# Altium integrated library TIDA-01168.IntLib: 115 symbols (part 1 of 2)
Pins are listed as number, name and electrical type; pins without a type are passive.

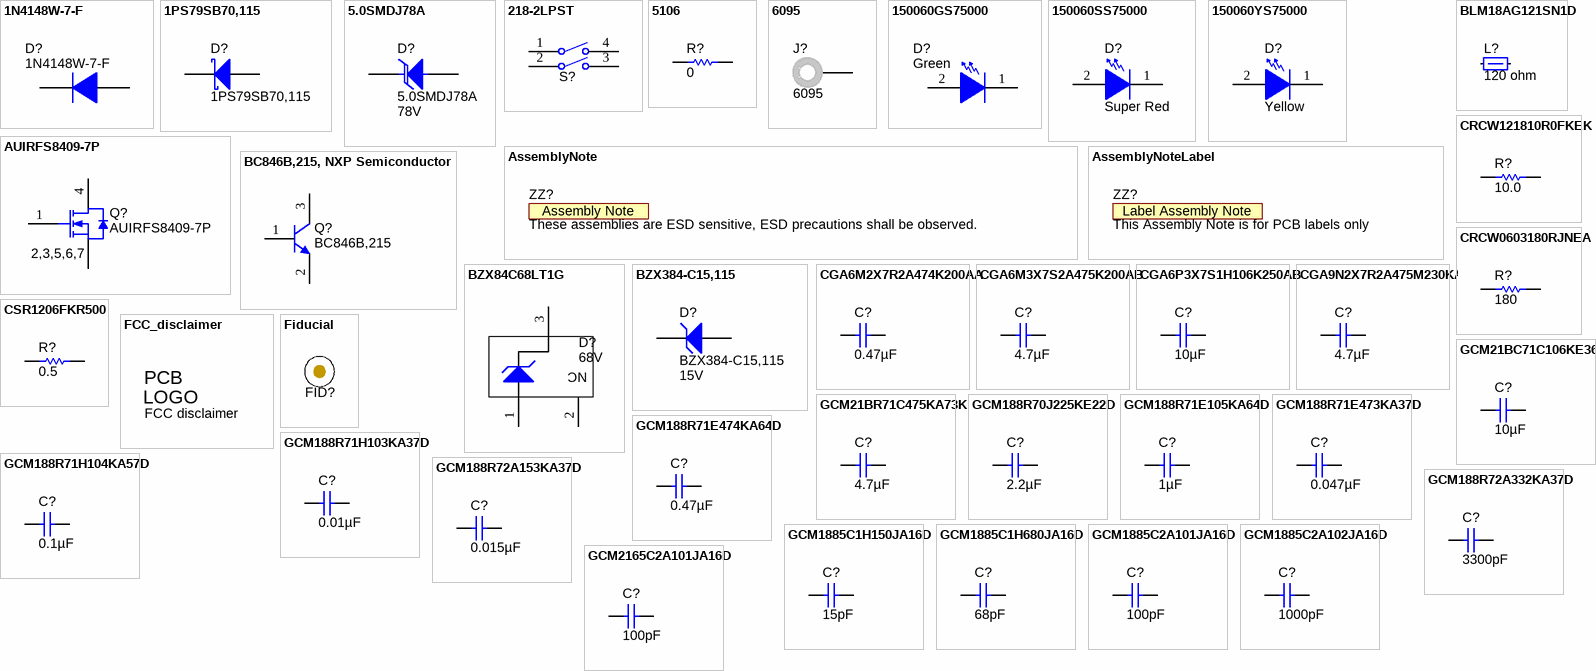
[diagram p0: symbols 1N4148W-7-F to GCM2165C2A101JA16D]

## 1N4148W-7-F
designator D?
Diode, Ultrafast, 100 V, 0.15 A, SOD-123; Manufacturer: Diodes Inc.; U/M: EA; Vf_V: 1.25; Value: 100V; Value1: 0.15A; Value2: 1.25V; Io_A: 0.15; Vr_V: 100; TJmax_C: 150; SizeAreaWB_mm2: 13.095; SizeArea_mm2: 6.545; SizeX_mm: 3.85; SizeY_mm: 1.7; SizeZ_mm: 1.35; AEC Category: Q101
signal-integrity model Diode
simulation model 1N4148W
footprint SOD-123
pins: 1 K, 2 A

## 1PS79SB70,115
designator D?
Diode, Schottky, 70 V, 0.07 A, SOD-523; Manufacturer: NXP Semiconductor; U/M: EA; Vf_V: 0.41; Value: 70V; Value1: 0.07A; Value2: 0.41V; Io_A: 0.07; Vr_V: 70; TJmax_C: 150; AEC Category: Q101
signal-integrity model Diode
footprint SOD-523
pins: 1 K, 2 A

## 5.0SMDJ78A
designator D?  value 78V
Diode, TVS, Uni, 78 V, 126 Vc, SMC; Manufacturer: Littelfuse; U/M: EA; Power_W: 6.5; Vr_V: 78; Value1: 6.5W; RJA_CperW: 75; SizeAreaWB_mm2: 83.2686; SizeArea_mm2: 50.5686; SizeX_mm: 8.13; SizeY_mm: 6.22; SizeZ_mm: 2.6; AEC Category: Q101
footprint SMC
pins: 1 K, 2 A

## 218-2LPST
designator S?  (value not drawn)
Switch, SPST, 2 Pos, 25mA, 24VDC, SMD; Manufacturer: CTS Electrocomponents; SymbolCreator: Altium; VDC_V: 24; SwitchFunction: Off-On; PositionCount: 2; CurrentRating_mA: 25
footprint SW_218-2LP
pins: 1, 2, 3, 4

## 5106
designator R?  ValueDisplayed: 0  (hidden comment: 5106)
RES, 0, 1%, 0.5 W, 0805; Manufacturer: Keystone; CompType: Resistor; Value: 0; Tolerance_%: 1; Power_W: 0.5; Value2: 0.5W; TempCo: ppm/C; SizeArea_mm2: 2.5; SizeX_mm: 2; SizeY_mm: 1.25; SizeZ_mm: 0.84; U/M: EA; AEC Category: Q200; AEC Qualified: N
signal-integrity model Resistor
simulation model Resistor
footprint 5106
pins: 1, 2

## 6095
designator J?
Standard Banana Jack, Uninsulated; Manufacturer: Keystone; CompType: Connector; SymbolCreator: a0412235
footprint Keystone_6095
pins: 1

## 150060GS75000
designator D?  value Green  (hidden comment: 150060GS75000)
LED, Green, SMD; Manufacturer: Wurth Elektronik; Type: InGaN; Vf_V: 3.2; Value2: 3.2V; Io_A: 0.02; Tjmax_C: 85; Value1: W; Angle: 140; U/M: EA
signal-integrity model Diode
footprint WL-SMCW_GREEN
pins: 1 K, 2 A

## 150060SS75000
designator D?  value Super Red  (hidden comment: 150060SS75000)
LED, Super Red, SMD; Manufacturer: Wurth Elektronik; Type: AlInGaP; Vf_V: 1.9; Value2: 1.9V; Io_A: 0.02; Value1: W; U/M: EA
signal-integrity model Diode
footprint WL-SMCW_RED
pins: 1 K, 2 A

## 150060YS75000
designator D?  value Yellow  (hidden comment: 150060YS75000)
LED, Yellow, SMD; Manufacturer: Wurth Elektronik; Type: AlInGaP; Vf_V: 2; Value2: 2V; Io_A: 0.02; Value1: W; U/M: EA
signal-integrity model Diode
footprint WL-SMCW_YELLOW
pins: 1 K, 2 A

## AssemblyNote
designator ZZ?, comment These assemblies are ESD sensitive, ESD precautions shall be observed.  (no BOM)
SymbolCreator: codlsc; CompType: AssemblyNote
footprint AssemblyNote

## AssemblyNoteLabel
designator ZZ?, comment This Assembly Note is for PCB labels only  (no BOM)
SymbolCreator: a0412235
footprint AssemblyNoteLabel

## AUIRFS8409-7P
designator Q?
MOSFET, N-CH, 40 V, 240 A, AEC-Q101, DDPAK-7; Manufacturer: Infineon Technologies; Alternate Manufacturer: None; U/M: EA; ChType: N; Value: 40V; VdsMax_V: 40; Value1: ? ohm; Value2: 305 nC; QgTyp_nC: 305; Vgs_V: 20; IdsMax_A: 240; SizeAreaWB_mm2: 209.6992; SizeArea_mm2: 154.8892; SizeX_mm: 15.245; SizeY_mm: 10.16; SizeZ_mm: 4.445; AEC Category: Q101; AEC Qualified: Y; SymbolCreator: a0412235
footprint DDPAK-7
pins: 1 G, 2 S, 3 S, 4 D, 5 S, 6 S, 7 S

## BC846B,215, NXP Semiconductor
designator Q?, comment BC846B,215
Transistor, NPN, 65 V, 0.1 A, SOT-23; Manufacturer: NXP Semiconductor; CompType: BJT; PNP: 0; NPN: 1; Vceo_V: 65; Vcesat1_V: 0.09; Value: 65 V; IcRated_A: 0.1; Value1: 0.1 A; HfeMax: 450; TaMin_C: -65; TaMax_C: 150; U/M: EA; AEC Category: Q101; AEC Qualified: N
footprint SOT-23
footprint SOT-23M
footprint SOT-23L
pins: 1 B, 2 E, 3 C

## BLM18AG121SN1D
designator L?  value 120 ohm  (hidden comment: BLM18AG121SN1D)
Ferrite Bead, 120 ohm @ 100 MHz, 0.5 A, 0603; Manufacturer: MuRata; Imax_A: 0.5; DCR_ohm: 0.18; Value1: 0.18 ohm; Value2: 0.5A; ZTyp@100MHz_Ohm: 120
footprint 0603
footprint 0603M
footprint 0603L
footprint 0603_HV
footprint 0603S
pins: 1, 2

## BZX84C68LT1G
designator D?  value 68V  (hidden comment: BZX84C68LT1G)
Diode, Zener, 68 V, 225 mW, SOT-23; Manufacturer: ON Semiconductor; U/M: EA; Power_W: 0.225; Vz_V: 68; Value1: 0.225W; RJA_CperW: 500; SizeAreaWB_mm2: 14; SizeArea_mm2: 7.5; SizeX_mm: 2.5; SizeY_mm: 3; SizeZ_mm: 1.1; AEC Category: Q101; AEC Qualified: N
signal-integrity model Diode
footprint SOT-23
footprint SOT-23M
footprint SOT-23L
pins: 1 A, 2 NC, 3 K
1 alternate drawing of the same symbol

## BZX384-C15,115
designator D?  value 15V
Diode, Zener, 15 V, 300 mW, SOD-323; Manufacturer: NXP Semiconductor; U/M: EA; Value1: 0.3W; AEC Category: Q101; SymbolCreator: a0412235; Power_W: 0.3; Vz_V: 15; RJA_CperW: 415; SizeAreaWB_mm2: 8.695; SizeArea_mm2: 3.645; SizeX_mm: 2.7; SizeY_mm: 1.35; SizeZ_mm: 1
signal-integrity model Diode
footprint SOD-323
pins: 1 K, 2 A

## CGA6M2X7R2A474K200AA
designator C?  ValueDisplayed: 0.47µF  (hidden comment: CGA6M2X7R2A474K200AA)
CAP, CERM, 0.47 µF, 100 V, +/- 10%, X7R, AEC-Q200 Grade 1, 1210; Manufacturer: TDK; Polarized: N; CompType: Capacitor; Value: 0.47uF; U/M: EA; Cap_F: 0.00000047; Tolerance_%: 10; ESR_ohm: 0.009164; Value1: 0.009164 ohm; VDC_V: 100; Value2: 100V; IRMS_A: 2.43674; TaMin_C: -55; TaMax_C: 125; Cap_Case: 1210_220; SizeArea_mm2: 8; SizeAreaWB_mm2: 14.7; SizeX_mm: 3.2; SizeY_mm: 2.5; SizeZ_mm: 2.2; AEC Category: Q200; AEC Qualified: Y; AEC Grade: 1
signal-integrity model Cap
simulation model Cap
footprint 1210_220
footprint 1210_220M
footprint 1210_220L
pins: 1, 2

## CGA6M3X7S2A475K200AB
designator C?  ValueDisplayed: 4.7µF  (hidden comment: CGA6M3X7S2A475K200AB)
CAP, CERM, 4.7 µF, 100 V, +/- 10%, X7S, AEC-Q200 Grade 1, 1210; Manufacturer: TDK; Polarized: N; CompType: Capacitor; Value: 4.7uF; U/M: EA; Cap_F: 0.0000047; Tolerance_%: 10; ESR_ohm: 0.004236; Value1: 0.004236 ohm; VDC_V: 100; Value2: 100V; IRMS_A: 3.57337; TaMin_C: -55; TaMax_C: 125; Cap_Case: 1210_220; SizeArea_mm2: 8; SizeAreaWB_mm2: 14.7; SizeX_mm: 3.2; SizeY_mm: 2.5; SizeZ_mm: 2.2; AEC Category: Q200; AEC Qualified: Y; AEC Grade: 1
signal-integrity model Cap
simulation model Cap
footprint 1210_220
footprint 1210_220M
footprint 1210_220L
pins: 1, 2

## CGA6P3X7S1H106K250AB
designator C?  ValueDisplayed: 10µF  (hidden comment: CGA6P3X7S1H106K250AB)
CAP, CERM, 10 µF, 50 V, +/- 10%, X7S, AEC-Q200 Grade 1, 1210; Manufacturer: TDK; Polarized: N; CompType: Capacitor; Value: 10uF; U/M: EA; Cap_F: 0.00001; Tolerance_%: 10; ESR_ohm: 0.002827; Value1: 0.002827 ohm; VDC_V: 50; Value2: 50V; IRMS_A: 4.37286; TaMin_C: -55; TaMax_C: 125; Cap_Case: 1210_280; SizeArea_mm2: 8; SizeAreaWB_mm2: 14.7; SizeX_mm: 3.2; SizeY_mm: 2.5; SizeZ_mm: 2.8; AEC Category: Q200; AEC Qualified: Y; AEC Grade: 1
signal-integrity model Cap
simulation model Cap
footprint 1210_280
pins: 1, 2

## CGA9N2X7R2A475M230KA
designator C?  ValueDisplayed: 4.7µF  (hidden comment: CGA9N2X7R2A475M230KA)
CAP, CERM, 4.7 µF, 100 V, +/- 20%, X7R, AEC-Q200 Grade 1,; Manufacturer: TDK; Polarized: N; CompType: Capacitor; Value: 4.7uF; U/M: EA; Cap_F: 0.0000047; Tolerance_%: 20; Value1: Unknown; VDC_V: 100; Value2: 100V; TaMin_C: -55; TaMax_C: 125; Cap_Case: 2220; SizeArea_mm2: 28.5; SizeAreaWB_mm2: 53.9; SizeX_mm: 5.7; SizeY_mm: 5; SizeZ_mm: 2.5; AEC Category: Q200; AEC Qualified: Y; AEC Grade: 1
signal-integrity model Cap
simulation model Cap
footprint 2220_250
footprint 2220_250M
footprint 2220_250L
pins: 1, 2

## CRCW121810R0FKEK
designator R?  ValueDisplayed: 10.0  (hidden comment: CRCW121810R0FKEK)
RES, 10.0, 1%, 1 W, 1218; Manufacturer: Vishay-Dale; CompType: Resistor; Value: 10.0; Res_ohm: 10; Value_Code: 10R0; Tolerance_%: 1; Value2: 1W; VDC_V: 200; TempCo: 100 ppm/C; SizeArea_mm2: 14.72; SizeAreaWB_mm2: 23.52; SizeX_mm: 3.2; SizeY_mm: 4.6; SizeZ_mm: 0.6; EIA_Code: E96; U/M: EA; AEC Category: Q200
signal-integrity model Resistor
simulation model Resistor
footprint 1218
pins: 1, 2

## CRCW0603180RJNEA
designator R?  ValueDisplayed: 180  (hidden comment: CRCW0603180RJNEA)
RES, 180, 5%, 0.1 W, 0603; Manufacturer: Vishay-Dale; CompType: Resistor; Value: 180; Value_Code: 180R; Tolerance_%: 5; Power_W: 0.1; Value2: 0.1W; VDC_V: 75; TempCo: 200 ppm/C; EIA_Code: E24; U/M: EA; AEC Category: Q200; SizeArea_mm2: 1.28; SizeX_mm: 1.6; SizeY_mm: 0.8; SizeZ_mm: 1
signal-integrity model Resistor
simulation model Resistor
footprint 0603
footprint 0603M
footprint 0603L
footprint 0603_HV
footprint 0603S
pins: 1, 2

## CSR1206FKR500
designator R?  ValueDisplayed: 0.5  (hidden comment: CSR1206FKR500)
RES, 0.5, 1%, 0.5 W, 1206; Manufacturer: Stackpole Electronics Inc; CompType: Resistor; Value: 0.5; Value_Code: R500; Tolerance_%: 1; Value2: 0.5W; TempCo: 100 ppm/C; U/M: EA; AEC Category: Q200; SizeArea_mm2: 5.12; SizeX_mm: 3.2; SizeY_mm: 1.6; SizeZ_mm: 1.35
signal-integrity model Resistor
simulation model Resistor
footprint 1206
footprint 1206M
footprint 1206L
pins: 1, 2

## FCC_disclaimer
designator Logo?, comment FCC disclaimer  (no BOM)
FCC_disclaimer; SymbolCreator: codlsc
footprint FCC_disclaimer
footprint FCC_disclaimer_stacked

## Fiducial
designator FID?  (value not drawn)
Fiducial mark.  There is nothing to buy or mount.; SymbolCreator: codlsc
footprint Fiducial10-30
footprint Fiducial10-20
footprint Fiducial15-30
footprint Fiducial20-40
footprint Fiducial6.4-20

## GCM21BC71C106KE36L
designator C?  ValueDisplayed: 10µF  (hidden comment: GCM21BC71C106KE36L)
CAP, CERM, 10 µF, 16 V, +/- 10%, X7S, AEC-Q200 Grade 1, 0805; Manufacturer: MuRata; Polarized: N; CompType: Capacitor; Value: 10uF; U/M: EA; Cap_F: 0.00001; Tolerance_%: 10; Value1: Unknown; VDC_V: 16; Value2: 16V; TaMin_C: -55; TaMax_C: 125; Cap_Case: 0805; AEC Category: Q200; AEC Qualified: Y; AEC Grade: 1; SizeArea_mm2: 2.5; SizeAreaWB_mm2: 6.75; SizeX_mm: 2; SizeY_mm: 1.25; SizeZ_mm: 1.45
signal-integrity model Cap
simulation model Cap
footprint 0805_HV
footprint 0805_HV1
footprint 0805
footprint 0805M
footprint 0805L
pins: 1, 2

## GCM21BR71C475KA73K
designator C?  ValueDisplayed: 4.7µF  (hidden comment: GCM21BR71C475KA73K)
CAP, CERM, 4.7 µF, 16 V, +/- 10%, X7R, AEC-Q200 Grade 1, 0805; Manufacturer: MuRata; Polarized: N; CompType: Capacitor; Value: 4.7uF; U/M: EA; Cap_F: 0.0000047; Tolerance_%: 10; Value1: Unknown; VDC_V: 16; Value2: 16V; TaMin_C: -55; TaMax_C: 125; Cap_Case: 0805; AEC Category: Q200; AEC Qualified: Y; AEC Grade: 1; SizeArea_mm2: 2.5; SizeAreaWB_mm2: 6.75; SizeX_mm: 2; SizeY_mm: 1.25; SizeZ_mm: 1.45
signal-integrity model Cap
simulation model Cap
footprint 0805_HV
footprint 0805_HV1
footprint 0805
footprint 0805M
footprint 0805L
pins: 1, 2

## GCM188R70J225KE22D
designator C?  ValueDisplayed: 2.2µF  (hidden comment: GCM188R70J225KE22D)
CAP, CERM, 2.2 µF, 6.3 V, +/- 10%, X7R, AEC-Q200 Grade 1, 0603; Manufacturer: MuRata; Polarized: N; CompType: Capacitor; Value: 2.2uF; U/M: EA; Cap_F: 0.0000022; Tolerance_%: 10; Value1: Unknown; VDC_V: 6.3; Value2: 6.3V; TaMin_C: -55; TaMax_C: 125; Cap_Case: 0603; AEC Category: Q200; AEC Qualified: Y; AEC Grade: 1; SizeArea_mm2: 1.28; SizeAreaWB_mm2: 4.68; SizeX_mm: 1.6; SizeY_mm: 0.8
signal-integrity model Cap
simulation model Cap
footprint 0603
footprint 0603M
footprint 0603L
footprint 0603_HV
footprint 0603S
pins: 1, 2

## GCM188R71E105KA64D
designator C?  ValueDisplayed: 1µF  (hidden comment: GCM188R71E105KA64D)
CAP, CERM, 1 µF, 25 V, +/- 10%, X7R, AEC-Q200 Grade 1, 0603; Manufacturer: MuRata; Polarized: N; CompType: Capacitor; Value: 1uF; U/M: EA; Cap_F: 0.000001; Tolerance_%: 10; Value1: Unknown; VDC_V: 25; Value2: 25V; TaMin_C: -55; TaMax_C: 125; Cap_Case: 0603; AEC Category: Q200; AEC Qualified: Y; AEC Grade: 1; SizeArea_mm2: 1.28; SizeAreaWB_mm2: 4.68; SizeX_mm: 1.6; SizeY_mm: 0.8
signal-integrity model Cap
simulation model Cap
footprint 0603
footprint 0603M
footprint 0603L
footprint 0603_HV
footprint 0603S
pins: 1, 2

## GCM188R71E473KA37D
designator C?  ValueDisplayed: 0.047µF  (hidden comment: GCM188R71E473KA37D)
CAP, CERM, 0.047 µF, 25 V, +/- 10%, X7R, AEC-Q200 Grade 1, 0603; Manufacturer: MuRata; Polarized: N; CompType: Capacitor; Value: 0.047uF; U/M: EA; Cap_F: 0.000000047; Tolerance_%: 10; Value1: Unknown; VDC_V: 25; Value2: 25V; TaMin_C: -55; TaMax_C: 125; Cap_Case: 0603; AEC Category: Q200; AEC Qualified: Y; AEC Grade: 1; SizeArea_mm2: 1.28; SizeAreaWB_mm2: 4.68; SizeX_mm: 1.6; SizeY_mm: 0.8
signal-integrity model Cap
simulation model Cap
footprint 0603
footprint 0603M
footprint 0603L
footprint 0603_HV
footprint 0603S
pins: 1, 2

## GCM188R71E474KA64D
designator C?  ValueDisplayed: 0.47µF  (hidden comment: GCM188R71E474KA64D)
CAP, CERM, 0.47 µF, 25 V, +/- 10%, X7R, AEC-Q200 Grade 1, 0603; Manufacturer: MuRata; Polarized: N; CompType: Capacitor; Value: 0.47uF; U/M: EA; Cap_F: 0.00000047; Tolerance_%: 10; Value1: Unknown; VDC_V: 25; Value2: 25V; TaMin_C: -55; TaMax_C: 125; Cap_Case: 0603; AEC Category: Q200; AEC Qualified: Y; AEC Grade: 1; SizeArea_mm2: 1.28; SizeAreaWB_mm2: 4.68; SizeX_mm: 1.6; SizeY_mm: 0.8
signal-integrity model Cap
simulation model Cap
footprint 0603
footprint 0603M
footprint 0603L
footprint 0603_HV
footprint 0603S
pins: 1, 2

## GCM188R71H103KA37D
designator C?  ValueDisplayed: 0.01µF  (hidden comment: GCM188R71H103KA37D)
CAP, CERM, 0.01 µF, 50 V, +/- 10%, X7R, AEC-Q200 Grade 1, 0603; Manufacturer: MuRata; Polarized: N; CompType: Capacitor; Value: 0.01uF; U/M: EA; Cap_F: 0.00000001; Tolerance_%: 10; Value1: Unknown; VDC_V: 50; Value2: 50V; TaMin_C: -55; TaMax_C: 125; Cap_Case: 0603; SizeArea_mm2: 1.28; SizeAreaWB_mm2: 4.68; SizeX_mm: 1.6; SizeY_mm: 0.8; SizeZ_mm: 1; AEC Category: Q200; AEC Qualified: Y
signal-integrity model Cap
simulation model Cap
footprint 0603
footprint 0603M
footprint 0603L
footprint 0603_HV
footprint 0603S
pins: 1, 2

## GCM188R71H104KA57D
designator C?  ValueDisplayed: 0.1µF  (hidden comment: GCM188R71H104KA57D)
CAP, CERM, 0.1 µF, 50 V, +/- 10%, X7R, 0603; Manufacturer: MuRata; Polarized: N; CompType: Capacitor; Value: 0.1uF; U/M: EA; Cap_F: 0.0000001; Tolerance_%: 10; ESR_ohm: 0.02; Value1: 0.02 ohm; VDC_V: 50; Value2: 50V; IRMS_A: 1.84; TaMin_C: -55; TaMax_C: 125; Cap_Case: 0603; SizeArea_mm2: 1.28; SizeAreaWB_mm2: 4.68; SizeX_mm: 1.6; SizeY_mm: 0.8; SizeZ_mm: 1; AEC Category: Q200
signal-integrity model Cap
simulation model Cap
footprint 0603
footprint 0603M
footprint 0603L
footprint 0603_HV
footprint 0603S
pins: 1, 2

## GCM188R72A153KA37D
designator C?  ValueDisplayed: 0.015µF  (hidden comment: GCM188R72A153KA37D)
CAP, CERM, 0.015 µF, 100 V, +/- 10%, X7R, AEC-Q200 Grade 1, 0603; Manufacturer: MuRata; Polarized: N; CompType: Capacitor; Value: 0.015uF; U/M: EA; Cap_F: 0.000000015; Tolerance_%: 10; Value1: Unknown; VDC_V: 100; Value2: 100V; TaMin_C: -55; TaMax_C: 125; Cap_Case: 0603; SizeArea_mm2: 1.28; SizeAreaWB_mm2: 4.68; SizeX_mm: 1.6; SizeY_mm: 0.8; SizeZ_mm: 1; AEC Category: Q200; AEC Qualified: Y
signal-integrity model Cap
simulation model Cap
footprint 0603
footprint 0603M
footprint 0603L
footprint 0603_HV
footprint 0603S
pins: 1, 2

## GCM188R72A332KA37D
designator C?  ValueDisplayed: 3300pF  (hidden comment: GCM188R72A332KA37D)
CAP, CERM, 3300 pF, 100 V, +/- 10%, X7R, AEC-Q200 Grade 1, 0603; Manufacturer: MuRata; Polarized: N; CompType: Capacitor; Value: 3300pF; U/M: EA; Cap_F: 0.0000000033; Tolerance_%: 10; Value1: Unknown; VDC_V: 100; Value2: 100V; TaMin_C: -55; TaMax_C: 125; Cap_Case: 0603; SizeArea_mm2: 1.28; SizeAreaWB_mm2: 4.68; SizeX_mm: 1.6; SizeY_mm: 0.8; SizeZ_mm: 1; AEC Category: Q200; AEC Qualified: Y
signal-integrity model Cap
simulation model Cap
footprint 0603
footprint 0603M
footprint 0603L
footprint 0603_HV
footprint 0603S
pins: 1, 2

## GCM1885C1H150JA16D
designator C?  ValueDisplayed: 15pF  (hidden comment: GCM1885C1H150JA16D)
CAP, CERM, 15 pF, 50 V, +/- 5%, C0G/NP0, AEC-Q200 Grade 1, 0603; Manufacturer: MuRata; Polarized: N; CompType: Capacitor; Value: 15pF; U/M: EA; Cap_F: 0.000000000015; Tolerance_%: 5; Value1: Unknown; VDC_V: 50; Value2: 50V; TaMin_C: -55; TaMax_C: 125; Cap_Case: 0603; SizeArea_mm2: 1.28; SizeAreaWB_mm2: 4.68; SizeX_mm: 1.6; SizeY_mm: 0.8; SizeZ_mm: 1; AEC Category: Q200; AEC Qualified: Y
signal-integrity model Cap
simulation model Cap
footprint 0603
footprint 0603M
footprint 0603L
footprint 0603_HV
footprint 0603S
pins: 1, 2

## GCM1885C1H680JA16D
designator C?  ValueDisplayed: 68pF  (hidden comment: GCM1885C1H680JA16D)
CAP, CERM, 68 pF, 50 V, +/- 5%, C0G/NP0, AEC-Q200 Grade 1, 0603; Manufacturer: MuRata; Polarized: N; CompType: Capacitor; Value: 68pF; U/M: EA; Cap_F: 0.000000000068; Tolerance_%: 5; Value1: Unknown; VDC_V: 50; Value2: 50V; TaMin_C: -55; TaMax_C: 125; Cap_Case: 0603; AEC Category: Q200; AEC Qualified: Y; AEC Grade: 1
signal-integrity model Cap
simulation model Cap
footprint 0603
footprint 0603M
footprint 0603L
footprint 0603_HV
footprint 0603S
pins: 1, 2

## GCM1885C2A101JA16D
designator C?  ValueDisplayed: 100pF  (hidden comment: GCM1885C2A101JA16D)
CAP, CERM, 100 pF, 100 V, +/- 5%, C0G/NP0, AEC-Q200 Grade 1, 0603; Manufacturer: MuRata; Polarized: N; CompType: Capacitor; Value: 100pF; U/M: EA; Cap_F: 0.0000000001; Tolerance_%: 5; Value1: Unknown; VDC_V: 100; Value2: 100V; TaMin_C: -55; TaMax_C: 125; Cap_Case: 0603; SizeArea_mm2: 1.28; SizeAreaWB_mm2: 4.68; SizeX_mm: 1.6; SizeY_mm: 0.8; SizeZ_mm: 1; AEC Category: Q200; AEC Qualified: Y
signal-integrity model Cap
simulation model Cap
footprint 0603
footprint 0603M
footprint 0603L
footprint 0603_HV
footprint 0603S
pins: 1, 2

## GCM1885C2A102JA16D
designator C?  ValueDisplayed: 1000pF  (hidden comment: GCM1885C2A102JA16D)
CAP, CERM, 1000 pF, 100 V, +/- 5%, C0G/NP0, AEC-Q200 Grade 1, 0603; Manufacturer: MuRata; Polarized: N; CompType: Capacitor; Value: 1000pF; U/M: EA; Cap_F: 0.000000001; Tolerance_%: 5; Value1: Unknown; VDC_V: 100; Value2: 100V; TaMin_C: -55; TaMax_C: 125; Cap_Case: 0603; SizeArea_mm2: 1.28; SizeAreaWB_mm2: 4.68; SizeX_mm: 1.6; SizeY_mm: 0.8; SizeZ_mm: 1; AEC Category: Q200; AEC Qualified: Y
signal-integrity model Cap
simulation model Cap
footprint 0603
footprint 0603M
footprint 0603L
footprint 0603_HV
footprint 0603S
pins: 1, 2

## GCM2165C2A101JA16D
designator C?  ValueDisplayed: 100pF  (hidden comment: GCM2165C2A101JA16D)
CAP, CERM, 100 pF, 100 V, +/- 5%, C0G/NP0, AEC-Q200 Grade 1, 0805; Manufacturer: MuRata; Polarized: N; CompType: Capacitor; Value: 100pF; U/M: EA; Cap_F: 0.0000000001; Tolerance_%: 5; Value1: Unknown; VDC_V: 100; Value2: 100V; TaMin_C: -55; TaMax_C: 105; Cap_Case: 0805; SizeArea_mm2: 2.5; SizeAreaWB_mm2: 6.75; SizeX_mm: 2; SizeY_mm: 1.25; SizeZ_mm: 1.45; AEC Category: Q200; AEC Qualified: Y; AEC Grade: 1
signal-integrity model Cap
simulation model Cap
footprint 0805_HV
footprint 0805_HV1
footprint 0805
footprint 0805M
footprint 0805L
pins: 1, 2

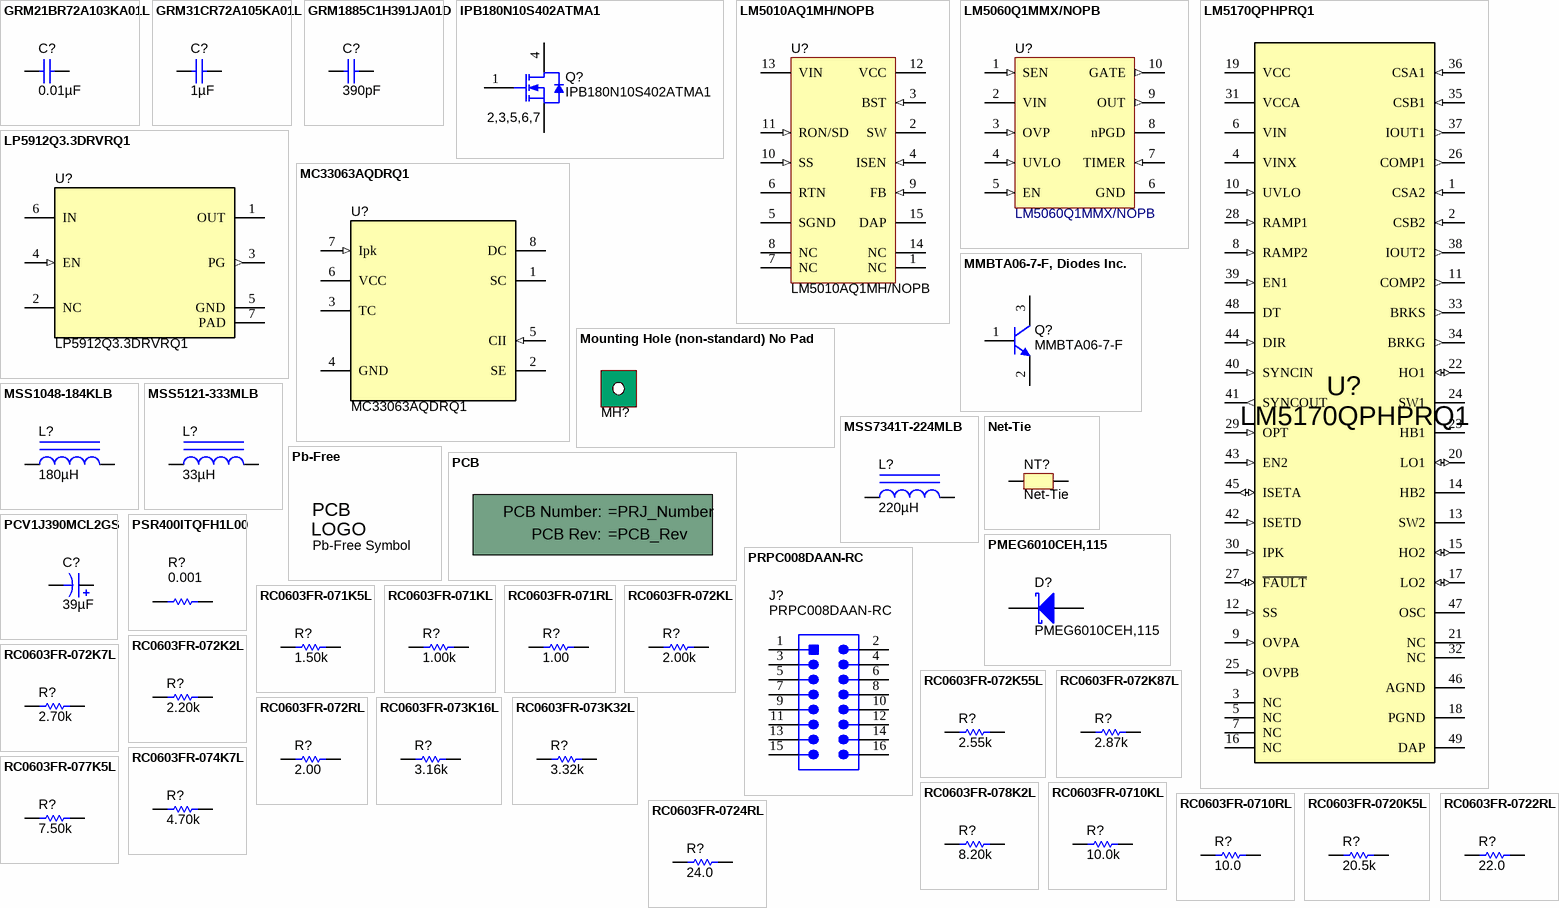
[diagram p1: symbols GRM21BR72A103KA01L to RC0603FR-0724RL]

## GRM21BR72A103KA01L
designator C?  ValueDisplayed: 0.01µF  (hidden comment: GRM21BR72A103KA01L)
CAP, CERM, 0.01 µF, 100 V, +/- 10%, X7R, 0805; Manufacturer: MuRata; Polarized: N; CompType: Capacitor; Value: 0.01uF; U/M: EA; Cap_F: 0.00000001; Tolerance_%: 10; Value1: Unknown; VDC_V: 100; Value2: 100V; TaMin_C: -55; TaMax_C: 125; Cap_Case: 0805; AEC Category: Q200; SizeArea_mm2: 2.5; SizeAreaWB_mm2: 6.75; SizeX_mm: 2; SizeY_mm: 1.25; SizeZ_mm: 1.45
signal-integrity model Cap
simulation model Cap
footprint 0805_HV
footprint 0805_HV1
footprint 0805
footprint 0805M
footprint 0805L
pins: 1, 2

## GRM31CR72A105KA01L
designator C?  ValueDisplayed: 1µF  (hidden comment: GRM31CR72A105KA01L)
CAP, CERM, 1 µF, 100 V, +/- 10%, X7R, 1206; Manufacturer: MuRata; Polarized: N; CompType: Capacitor; Value: 1uF; U/M: EA; Cap_F: 0.000001; Tolerance_%: 10; Value1: Unknown; VDC_V: 100; Value2: 100V; TaMin_C: -55; TaMax_C: 125; Cap_Case: 2220; AEC Category: Q200; SizeArea_mm2: 5.12; SizeAreaWB_mm2: 10.92; SizeX_mm: 3.2; SizeY_mm: 1.6; SizeZ_mm: 1.8
signal-integrity model Cap
simulation model Cap
footprint 1206_180
footprint 1206_180M
footprint 1206_180L
pins: 1, 2

## GRM1885C1H391JA01D
designator C?  ValueDisplayed: 390pF  (hidden comment: GRM1885C1H391JA01D)
CAP, CERM, 390 pF, 50 V, +/- 5%, C0G/NP0, 0603; Manufacturer: MuRata; Polarized: N; CompType: Capacitor; Value: 390pF; U/M: EA; Cap_F: 0.00000000039; Tolerance_%: 5; Value1: Unknown; VDC_V: 50; Value2: 50V; TaMin_C: -55; TaMax_C: 125; Cap_Case: 0603; SizeArea_mm2: 1.28; SizeAreaWB_mm2: 4.68; SizeX_mm: 1.6; SizeY_mm: 0.8; SizeZ_mm: 1; AEC Category: Q200
signal-integrity model Cap
simulation model Cap
footprint 0603
footprint 0603M
footprint 0603L
footprint 0603_HV
footprint 0603S
pins: 1, 2

## IPB180N10S402ATMA1
designator Q?
MOSFET, N-CH, 100 V, 180 A, AEC-Q101, DDPAK-7; Manufacturer: Infineon Technologies; Alternate Manufacturer: None; U/M: EA; ChType: N; Value: 100V; VdsMax_V: 100; Value1: ? ohm; Value2: 156 nC; QgTyp_nC: 156; Vgs_V: 20; IdsMax_A: 180; SizeAreaWB_mm2: 209.6992; SizeArea_mm2: 154.8892; SizeX_mm: 15.245; SizeY_mm: 10.16; SizeZ_mm: 4.445; AEC Category: Q101; AEC Qualified: Y; SymbolCreator: a0412235
footprint DDPAK-7
pins: 1 G, 2 S, 3 S, 4 D, 5 S, 6 S, 7 S

## LM5010AQ1MH/NOPB
designator U?
High Voltage 1A Step Down Switching Regulator, 14-pin TSSOP-EP, Pb-Free; Manufacturer: Texas Instruments; PackageTopMarking: NSUZXYTT*L5010A*Q1MH; PowerWise: N; CompType: Switcher
footprint MXA14A_N (TSOP, 14-Leads, Body 5x4.4mm, Pitch 0.65mm, Exposed Pad, IPC Medium Density)
footprint MXA14A_L (TSOP, 14-Leads, Body 5x4.4mm, Pitch 0.65mm, Exposed Pad, IPC High Density)
footprint MXA14A_M (TSOP, 14-Leads, Body 5x4.4mm, Pitch 0.65mm, Exposed Pad, IPC Low Density)
pins: 1 NC, 2 SW (power), 3 BST (in), 4 ISEN (in), 5 SGND (power), 6 RTN (power), 7 NC, 8 NC, 9 FB (in), 10 SS (in), 11 RON/SD (in), 12 VCC (power), 13 VIN (power), 14 NC, 15 DAP (power)

## LM5060Q1MMX/NOPB
designator U?
High-Side Protection Controller with Low Quiescent Current, 10-pin MSOP, Pb-Free; Manufacturer: Texas Instruments; PackageTopMarking: ZXTT*SZAB; PowerWise: N; CompType: Switcher
footprint MUB10A_N (TSSOP, 10-Leads, Body 3x3mm, Pitch 0.5mm, IPC Medium Density)
footprint MUB10A_L (TSSOP, 10-Leads, Body 3x3mm, Pitch 0.5mm, IPC High Density)
footprint MUB10A_M (TSSOP, 10-Leads, Body 3x3mm, Pitch 0.5mm, IPC Low Density)
pins: 1 SEN (in), 2 VIN (power), 3 OVP (in), 4 UVLO (in), 5 EN (in), 6 GND (power), 7 TIMER (in), 8 nPGD (oc), 9 OUT (out), 10 GATE (out)

## LM5170QPHPRQ1
designator U?
Dual Channel 48V-12V Bidirectional Current Controller, PHP0048D; Alternate PartNumber: LM5170QPHPTQ1; Manufacturer: Texas Instruments; SymbolCreator: Altium; SizeArea_mm2: 81; SizeAreaWB_mm2: 121; SizeX_mm: 9; SizeZ_mm: 1.2; CompType: IC; U/M: EA
footprint PHP0048D_N
footprint PHP0048D_M
footprint PHP0048D_L
pins: 1 CSA2 (in), 2 CSB2 (in), 3 NC, 4 VINX (power), 5 NC, 6 VIN (power), 7 NC, 8 RAMP2 (in), 9 OVPA (in), 10 UVLO (in), 11 COMP2 (out), 12 SS (in), 13 SW2 (power), 14 HB2 (power), 15 HO2 (io), 16 NC, 17 LO2 (io), 18 PGND (power), 19 VCC (power), 20 LO1 (io), 21 NC, 22 HO1 (io), 23 HB1 (power), 24 SW1 (power), 25 OVPB (in), 26 COMP1 (out), 27 ~{FAULT} (io), 28 RAMP1 (in), 29 OPT (in), 30 IPK (in), 31 VCCA (power), 32 NC, 33 BRKS (out), 34 BRKG (out), 35 CSB1 (in), 36 CSA1 (in), 37 IOUT1 (out), 38 IOUT2 (out), 39 EN1 (in), 40 SYNCIN (in), 41 SYNCOUT (out), 42 ISETD (in), 43 EN2 (in), 44 DIR (in), 45 ISETA (io), 46 AGND (power), 47 OSC, 48 DT, 49 DAP (power)
1 alternate drawing of the same symbol

## LP5912Q3.3DRVRQ1
designator U?
Ultra Low-Noise, 500-mA Linear Regulator for RF and Analog Circuits - Requires No Bypass Capacitor, DRV0006A; Alternate PartNumber: LP5912Q3.3DRVTQ1; Manufacturer: Texas Instruments; SymbolCreator: a0411947; SizeArea_mm2: 4; SizeAreaWB_mm2: 9; SizeX_mm: 2; SizeZ_mm: 0.8; CompType: IC; U/M: EA
footprint DRV0006A
footprint DRV0006A_NV
pins: 1 OUT (power), 2 NC, 3 PG (out), 4 EN (in), 5 GND (power), 6 IN (power), 7 PAD (power)

## MC33063AQDRQ1
designator U?
1.5-A PEAK BOOST / BUCK / INVERTING SWITCHING REGULATOR, D0008A; Manufacturer: Texas Instruments; SymbolCreator: Altium; SizeArea_mm2: 30.38; SizeAreaWB_mm2: 56.58; SizeX_mm: 4.9; SizeY_mm: 6.2; SizeZ_mm: 1.75; CompType: IC; U/M: EA
footprint D0008A_N
footprint D0008A_M
footprint D0008A_L
pins: 1 SC (oc) "Switch Collector", 2 SE (oe) "Switch Emitter", 3 TC "Timing Capacitor", 4 GND (power), 5 CII (in) "Comparator Inverting Input", 6 VCC (power), 7 Ipk (in), 8 DC (oc) "Driver Collector"

## MMBTA06-7-F, Diodes Inc.
designator Q?, comment MMBTA06-7-F
Transistor, NPN, 80 V, 0.5 A, SOT-23; Manufacturer: Diodes Inc.; CompType: BJT; PNP: 0; NPN: 1; Vceo_V: 80; Vcesat1_V: 0.25; Value: 80 V; IcRated_A: 0.5; Value1: 0.5 A; TaMin_C: -55; TaMax_C: 150; U/M: EA; AEC Category: Q101
footprint SOT-23
footprint SOT-23M
footprint SOT-23L
pins: 1 B, 2 E, 3 C

## Mounting Hole (non-standard) No Pad
designator MH?, comment MTG_NoPads  (value not drawn)  (no BOM)
PCB Mounting Hole, No Pad; Manufacturer: Any; SymbolCreator: a0412235
footprint MTG_159mil
footprint NPTH125mil
footprint NPTH109mil

## MSS1048-184KLB
designator L?  ValueDisplayed: 180µH  (hidden comment: MSS1048-184KLB)
Inductor, Shielded Drum Core, Ferrite, 180 µH, 1.02 A, 0.45 ohm, SMD; Manufacturer: Coilcraft; Value: 180uH; Ind_H: 180.0E-6; Imax_A: 1.02; Irms: 1.24A @ 40C rise; Isat: 1.02A @ 30% inductance drop; DCR_ohm: 0.45; Value2: 1.02A; AEC Category: Q200
signal-integrity model Inductor
simulation model Inductor
footprint MSS1048
pins: 1, 2

## MSS5121-333MLB
designator L?  ValueDisplayed: 33µH  (hidden comment: MSS5121-333MLB)
Inductor, Shielded Drum Core, Ferrite, 33 µH, 0.67 A, 0.48 ohm, SMD; Manufacturer: Coilcraft; Value: 33uH; Ind_H: 33.0E-6; Imax_A: 0.67; Irms: 0.76A @ 40C rise; Isat: 0.67A @ 30% inductance drop; DCR_ohm: 0.48; Value2: 0.67A; AEC Category: Q200
signal-integrity model Inductor
simulation model Inductor
footprint MSS5121
pins: 1, 2

## MSS7341T-224MLB
designator L?  ValueDisplayed: 220µH  (hidden comment: MSS7341T-224MLB)
Inductor, Shielded Drum Core, Ferrite, 220 µH, 0.51 A, 0.65 ohm, AEC-Q200 Grade 1, SMD; Manufacturer: Coilcraft; Value: 220uH; Ind_H: 220.0E-6; Imax_A: 0.51; Irms: 0.78A @ 40C rise; Isat: 0.51A @ 30% inductance drop; DCR_ohm: 0.65; Value2: 0.51A; AEC Category: Q200; AEC Qualified: Y; AEC Grade: 1
signal-integrity model Inductor
simulation model Inductor
footprint MSS7341
pins: 1, 2

## Net-Tie
designator NT?  (net tie, no BOM)
Single point connection between nets.; SymbolCreator: codlsc
footprint Net-Tie_10mil (10mil net tie, no solder mask opening, no solder paste)
footprint NetTie_1206 (1206 pads tied by 10mil copper trace which can be cut.  Part can be placed on pads.)
footprint Net-Tie_0805_HV
footprint NetTie_1206_NoOverlay (1206 pads tied by 10mil copper trace which can be cut.  Part can be placed on pads.)
footprint Net-Tie_0805_HV_NoOverlay (0805_HV pads tied by 10mil copper trace which can be cut.  An 0805 part can be placed on pads.)
footprint Net-Tie_10milWide_30milLong
footprint Net-Tie_20milWide_60milLong
footprint NetTie_0603
footprint NetTie_0402
footprint Net-Tie_50milWide_30milLong
pins: 1, 2

## Pb-Free
designator Logo?, comment Pb-Free Symbol  (no BOM)
SymbolCreator: a0412235
footprint Pb-Free_Overlay_Medium
footprint Pb-Free_Overlay_Small

## PCB
designator !PCB?, comment Printed Circuit Board  (value not drawn)  (mechanical)
Manufacturer: Any; SymbolCreator: a0412235; CompType: PCB
1 alternate drawing of the same symbol

## PCV1J390MCL2GS
designator C?  ValueDisplayed: 39µF  (hidden comment: PCV1J390MCL2GS)
CAP, Aluminum Polymer, 39 µF, 63 V, +/- 20%, 0.029 ohm, AEC-Q200 Grade 2, D8xL12mm SMD; Manufacturer: Nichicon; Polarized: Y; CompType: Capacitor; Value: 39uF; U/M: EA; Cap_F: 0.000039; Tolerance_%: 20; VDC_V: 63; Value2: 63V; ESR_ohm: 0.029; IRMS_A: 3.4; TaMin_C: -55; TaMax_C: 105; Cap_Case: 8x12mm; AEC Category: Q200; AEC Grade: 2
signal-integrity model Cap
simulation model Cap
footprint PCV_800x1200
pins: 1 +, 2 -

## PMEG6010CEH,115
designator D?
Diode, Schottky, 60 V, 1 A, SOD-123F; Manufacturer: NXP Semiconductor; U/M: EA; Vf_V: 0.57; Value: 60V; Value1: 1A; Value2: 0.57V; Io_A: 1; Vr_V: 60; TJmax_C: 150; SizeAreaWB_mm2: 11.7; SizeArea_mm2: 5.6; SizeX_mm: 3.5; SizeY_mm: 1.6; SizeZ_mm: 1.1; AEC Category: Q101
signal-integrity model Diode
footprint SOD-123F
pins: 1 K, 2 A

## PRPC008DAAN-RC
designator J?
Header, 2.54mm, 8x2, Gold, TH; Manufacturer: Sullins Connector Solutions; SymbolCreator: a0412235; U/M: EA
footprint Sullins_xxxC008DAAN
pins: 1, 2, 3, 4, 5, 6, 7, 8, 9, 10, 11, 12, 13, 14, 15, 16

## PSR400ITQFH1L00
designator R?  ValueDisplayed: 0.001  (hidden comment: PSR400ITQFH1L00)
RES, 0.001, 1%, 4 W, AEC-Q200 Grade 0, 10x5.2mm; Manufacturer: Rohm; CompType: Resistor; Value: 0.001; Value_Code: 1L000; Tolerance_%: 1; Power_W: 4; Value2: 4W; TempCo: 75 ppm/C; SizeArea_mm2: 52; SizeAreaWB_mm2: 86.4; SizeX_mm: 10; SizeY_mm: 5.2; SizeZ_mm: 1.05; EIA_Code: E96; U/M: EA; AEC Category: Q200; AEC Qualified: Y; AEC Grade: 0
signal-integrity model Resistor
simulation model Resistor
footprint 3921_105
pins: 1, 2

## RC0603FR-071K5L
designator R?  ValueDisplayed: 1.50k  (hidden comment: RC0603FR-071K5L)
RES, 1.50 k, 1%, 0.1 W, 0603; Manufacturer: Yageo America; CompType: Resistor; Value: 1.50k; Res_ohm: 1500; Value_Code: 1k50; Tolerance_%: 1; Power_W: 0.1; Value2: 0.1W; VDC_V: 150; TempCo: 200 ppm/C; EIA_Code: E96; U/M: EA; AEC Category: Q200; SizeArea_mm2: 1.28; SizeX_mm: 1.6; SizeY_mm: 0.8
signal-integrity model Resistor
simulation model Resistor
footprint 0603
footprint 0603M
footprint 0603L
footprint 0603_HV
footprint 0603S
pins: 1, 2

## RC0603FR-071KL
designator R?  ValueDisplayed: 1.00k  (hidden comment: RC0603FR-071KL)
RES, 1.00 k, 1%, 0.1 W, 0603; Manufacturer: Yageo America; CompType: Resistor; Value: 1.00k; Res_ohm: 1000; Value_Code: 1k00; Tolerance_%: 1; Power_W: 0.1; Value2: 0.1W; VDC_V: 150; TempCo: 200 ppm/C; EIA_Code: E96; U/M: EA; AEC Category: Q200; SizeArea_mm2: 1.28; SizeX_mm: 1.6; SizeY_mm: 0.8
signal-integrity model Resistor
simulation model Resistor
footprint 0603
footprint 0603M
footprint 0603L
footprint 0603_HV
footprint 0603S
pins: 1, 2

## RC0603FR-071RL
designator R?  ValueDisplayed: 1.00  (hidden comment: RC0603FR-071RL)
RES, 1.00, 1%, 0.1 W, 0603; Manufacturer: Yageo America; CompType: Resistor; Value: 1.00; Res_ohm: 1; Value_Code: 1R00; Power_W: 0.1; Value2: 0.1W; VDC_V: 150; TempCo: 200 ppm/C; SizeArea_mm2: 1.28; SizeX_mm: 1.6; SizeY_mm: 0.8; EIA_Code: E96; U/M: EA; AEC Category: Q200
signal-integrity model Resistor
simulation model Resistor
footprint 0603
footprint 0603M
footprint 0603L
footprint 0603_HV
footprint 0603S
pins: 1, 2

## RC0603FR-072K2L
designator R?  ValueDisplayed: 2.20k  (hidden comment: RC0603FR-072K2L)
RES, 2.20 k, 1%, 0.1 W, 0603; Manufacturer: Yageo America; CompType: Resistor; Value: 2.20k; Res_ohm: 2200; Value_Code: 2k20; Tolerance_%: 1; Power_W: 0.1; Value2: 0.1W; VDC_V: 150; TempCo: 200 ppm/C; U/M: EA; AEC Category: Q200; SizeArea_mm2: 1.28; SizeX_mm: 1.6; SizeY_mm: 0.8
signal-integrity model Resistor
simulation model Resistor
footprint 0603
footprint 0603M
footprint 0603L
footprint 0603_HV
footprint 0603S
pins: 1, 2

## RC0603FR-072K7L
designator R?  ValueDisplayed: 2.70k  (hidden comment: RC0603FR-072K7L)
RES, 2.70 k, 1%, 0.1 W, 0603; Manufacturer: Yageo America; CompType: Resistor; Value: 2.70k; Res_ohm: 2700; Value_Code: 2k70; Tolerance_%: 1; Power_W: 0.1; Value2: 0.1W; VDC_V: 150; TempCo: 200 ppm/C; U/M: EA; AEC Category: Q200; SizeArea_mm2: 1.28; SizeX_mm: 1.6; SizeY_mm: 0.8
signal-integrity model Resistor
simulation model Resistor
footprint 0603
footprint 0603M
footprint 0603L
footprint 0603_HV
footprint 0603S
pins: 1, 2

## RC0603FR-072K55L
designator R?  ValueDisplayed: 2.55k  (hidden comment: RC0603FR-072K55L)
RES, 2.55 k, 1%, 0.1 W, 0603; Manufacturer: Yageo America; CompType: Resistor; Value: 2.55k; Res_ohm: 2550; Value_Code: 2k55; Tolerance_%: 1; Power_W: 0.1; Value2: 0.1W; VDC_V: 150; TempCo: 200 ppm/C; EIA_Code: E96; U/M: EA; AEC Category: Q200; SizeArea_mm2: 1.28; SizeX_mm: 1.6; SizeY_mm: 0.8
signal-integrity model Resistor
simulation model Resistor
footprint 0603
footprint 0603M
footprint 0603L
footprint 0603_HV
footprint 0603S
pins: 1, 2

## RC0603FR-072K87L
designator R?  ValueDisplayed: 2.87k  (hidden comment: RC0603FR-072K87L)
RES, 2.87 k, 1%, 0.1 W, 0603; Manufacturer: Yageo America; CompType: Resistor; Value: 2.87k; Res_ohm: 2870; Value_Code: 2k87; Tolerance_%: 1; Power_W: 0.1; Value2: 0.1W; VDC_V: 150; TempCo: 200 ppm/C; EIA_Code: E96; U/M: EA; AEC Category: Q200; SizeArea_mm2: 1.28; SizeX_mm: 1.6; SizeY_mm: 0.8
signal-integrity model Resistor
simulation model Resistor
footprint 0603
footprint 0603M
footprint 0603L
footprint 0603_HV
footprint 0603S
pins: 1, 2

## RC0603FR-072KL
designator R?  ValueDisplayed: 2.00k  (hidden comment: RC0603FR-072KL)
RES, 2.00 k, 1%, 0.1 W, 0603; Manufacturer: Yageo America; CompType: Resistor; Value: 2.00k; Res_ohm: 2000; Value_Code: 2k00; Tolerance_%: 1; Power_W: 0.1; Value2: 0.1W; VDC_V: 150; TempCo: 200 ppm/C; EIA_Code: E96; U/M: EA; AEC Category: Q200; SizeArea_mm2: 1.28; SizeX_mm: 1.6; SizeY_mm: 0.8
signal-integrity model Resistor
simulation model Resistor
footprint 0603
footprint 0603M
footprint 0603L
footprint 0603_HV
footprint 0603S
pins: 1, 2

## RC0603FR-072RL
designator R?  ValueDisplayed: 2.00  (hidden comment: RC0603FR-072RL)
RES, 2.00, 1%, 0.1 W, 0603; Manufacturer: Yageo America; CompType: Resistor; Value: 2.00; Res_ohm: 2; Value_Code: 2R00; Tolerance_%: 1; Power_W: 0.1; Value2: 0.1W; VDC_V: 150; TempCo: 200 ppm/C; EIA_Code: E96; U/M: EA; AEC Category: Q200; SizeArea_mm2: 1.28; SizeX_mm: 1.6; SizeY_mm: 0.8
signal-integrity model Resistor
simulation model Resistor
footprint 0603
footprint 0603M
footprint 0603L
footprint 0603_HV
footprint 0603S
pins: 1, 2

## RC0603FR-073K16L
designator R?  ValueDisplayed: 3.16k  (hidden comment: RC0603FR-073K16L)
RES, 3.16 k, 1%, 0.1 W, 0603; Manufacturer: Yageo America; CompType: Resistor; Value: 3.16k; Res_ohm: 3160; Value_Code: 3k16; Tolerance_%: 1; Power_W: 0.1; Value2: 0.1W; VDC_V: 150; TempCo: 200 ppm/C; EIA_Code: E96; U/M: EA; AEC Category: Q200; SizeArea_mm2: 1.28; SizeX_mm: 1.6; SizeY_mm: 0.8
signal-integrity model Resistor
simulation model Resistor
footprint 0603
footprint 0603M
footprint 0603L
footprint 0603_HV
footprint 0603S
pins: 1, 2

## RC0603FR-073K32L
designator R?  ValueDisplayed: 3.32k  (hidden comment: RC0603FR-073K32L)
RES, 3.32 k, 1%, 0.1 W, 0603; Manufacturer: Yageo America; CompType: Resistor; Value: 3.32k; Res_ohm: 3320; Value_Code: 3k32; Tolerance_%: 1; Power_W: 0.1; Value2: 0.1W; VDC_V: 150; TempCo: 200 ppm/C; EIA_Code: E96; U/M: EA; AEC Category: Q200; SizeArea_mm2: 1.28; SizeX_mm: 1.6; SizeY_mm: 0.8
signal-integrity model Resistor
simulation model Resistor
footprint 0603
footprint 0603M
footprint 0603L
footprint 0603_HV
footprint 0603S
pins: 1, 2

## RC0603FR-074K7L
designator R?  ValueDisplayed: 4.70k  (hidden comment: RC0603FR-074K7L)
RES, 4.70 k, 1%, 0.1 W, 0603; Manufacturer: Yageo America; CompType: Resistor; Value: 4.70k; Res_ohm: 4700; Value_Code: 4k70; Tolerance_%: 1; Power_W: 0.1; Value2: 0.1W; VDC_V: 150; TempCo: 200 ppm/C; U/M: EA; AEC Category: Q200; SizeArea_mm2: 1.28; SizeX_mm: 1.6; SizeY_mm: 0.8
signal-integrity model Resistor
simulation model Resistor
footprint 0603
footprint 0603M
footprint 0603L
footprint 0603_HV
footprint 0603S
pins: 1, 2

## RC0603FR-077K5L
designator R?  ValueDisplayed: 7.50k  (hidden comment: RC0603FR-077K5L)
RES, 7.50 k, 1%, 0.1 W, 0603; Manufacturer: Yageo America; CompType: Resistor; Value: 7.50k; Res_ohm: 7500; Value_Code: 7k50; Tolerance_%: 1; Power_W: 0.1; Value2: 0.1W; VDC_V: 150; TempCo: 200 ppm/C; EIA_Code: E96; U/M: EA; AEC Category: Q200; SizeArea_mm2: 1.28; SizeX_mm: 1.6; SizeY_mm: 0.8
signal-integrity model Resistor
simulation model Resistor
footprint 0603
footprint 0603M
footprint 0603L
footprint 0603_HV
footprint 0603S
pins: 1, 2

## RC0603FR-078K2L
designator R?  ValueDisplayed: 8.20k  (hidden comment: RC0603FR-078K2L)
RES, 8.20 k, 1%, 0.1 W, 0603; Manufacturer: Yageo America; CompType: Resistor; Value: 8.20k; Res_ohm: 8200; Value_Code: 8k20; Tolerance_%: 1; Power_W: 0.1; Value2: 0.1W; VDC_V: 150; TempCo: 200 ppm/C; U/M: EA; AEC Category: Q200; SizeArea_mm2: 1.28; SizeX_mm: 1.6; SizeY_mm: 0.8
signal-integrity model Resistor
simulation model Resistor
footprint 0603
footprint 0603M
footprint 0603L
footprint 0603_HV
footprint 0603S
pins: 1, 2

## RC0603FR-0710KL
designator R?  ValueDisplayed: 10.0k  (hidden comment: RC0603FR-0710KL)
RES, 10.0 k, 1%, 0.1 W, 0603; Manufacturer: Yageo America; CompType: Resistor; Value: 10.0k; Res_ohm: 10000; Value_Code: 10k0; Tolerance_%: 1; Power_W: 0.1; Value2: 0.1W; VDC_V: 150; TempCo: 200 ppm/C; EIA_Code: E96; U/M: EA; AEC Category: Q200; SizeArea_mm2: 1.28; SizeX_mm: 1.6; SizeY_mm: 0.8
signal-integrity model Resistor
simulation model Resistor
footprint 0603
footprint 0603M
footprint 0603L
footprint 0603_HV
footprint 0603S
pins: 1, 2

## RC0603FR-0710RL
designator R?  ValueDisplayed: 10.0  (hidden comment: RC0603FR-0710RL)
RES, 10.0, 1%, 0.1 W, 0603; Manufacturer: Yageo America; CompType: Resistor; Value: 10.0; Res_ohm: 10; Value_Code: 10R0; Tolerance_%: 1; Power_W: 0.1; Value2: 0.1W; VDC_V: 150; TempCo: 200 ppm/C; EIA_Code: E96; U/M: EA; AEC Category: Q200; SizeArea_mm2: 1.28; SizeX_mm: 1.6; SizeY_mm: 0.8
signal-integrity model Resistor
simulation model Resistor
footprint 0603
footprint 0603M
footprint 0603L
footprint 0603_HV
footprint 0603S
pins: 1, 2

## RC0603FR-0720K5L
designator R?  ValueDisplayed: 20.5k  (hidden comment: RC0603FR-0720K5L)
RES, 20.5 k, 1%, 0.1 W, 0603; Manufacturer: Yageo America; CompType: Resistor; Value: 20.5k; Res_ohm: 20500; Value_Code: 20k5; Tolerance_%: 1; Power_W: 0.1; Value2: 0.1W; VDC_V: 150; TempCo: 200 ppm/C; EIA_Code: E96; U/M: EA; AEC Category: Q200; SizeArea_mm2: 1.28; SizeX_mm: 1.6; SizeY_mm: 0.8
signal-integrity model Resistor
simulation model Resistor
footprint 0603
footprint 0603M
footprint 0603L
footprint 0603_HV
footprint 0603S
pins: 1, 2

## RC0603FR-0722RL
designator R?  ValueDisplayed: 22.0  (hidden comment: RC0603FR-0722RL)
RES, 22.0, 1%, 0.1 W, 0603; Manufacturer: Yageo America; CompType: Resistor; Value: 22.0; Res_ohm: 22; Value_Code: 22R0; Tolerance_%: 1; Power_W: 0.1; Value2: 0.1W; VDC_V: 150; TempCo: 200 ppm/C; U/M: EA; AEC Category: Q200; SizeArea_mm2: 1.28; SizeX_mm: 1.6; SizeY_mm: 0.8
signal-integrity model Resistor
simulation model Resistor
footprint 0603
footprint 0603M
footprint 0603L
footprint 0603_HV
footprint 0603S
pins: 1, 2

## RC0603FR-0724RL
designator R?  ValueDisplayed: 24.0  (hidden comment: RC0603FR-0724RL)
RES, 24.0, 1%, 0.1 W, 0603; Manufacturer: Yageo America; CompType: Resistor; Value: 24.0; Res_ohm: 24; Value_Code: 24R0; Tolerance_%: 1; Power_W: 0.1; Value2: 0.1W; VDC_V: 150; TempCo: 200 ppm/C; U/M: EA; AEC Category: Q200; SizeArea_mm2: 1.28; SizeX_mm: 1.6; SizeY_mm: 0.8
signal-integrity model Resistor
simulation model Resistor
footprint 0603
footprint 0603M
footprint 0603L
footprint 0603_HV
footprint 0603S
pins: 1, 2

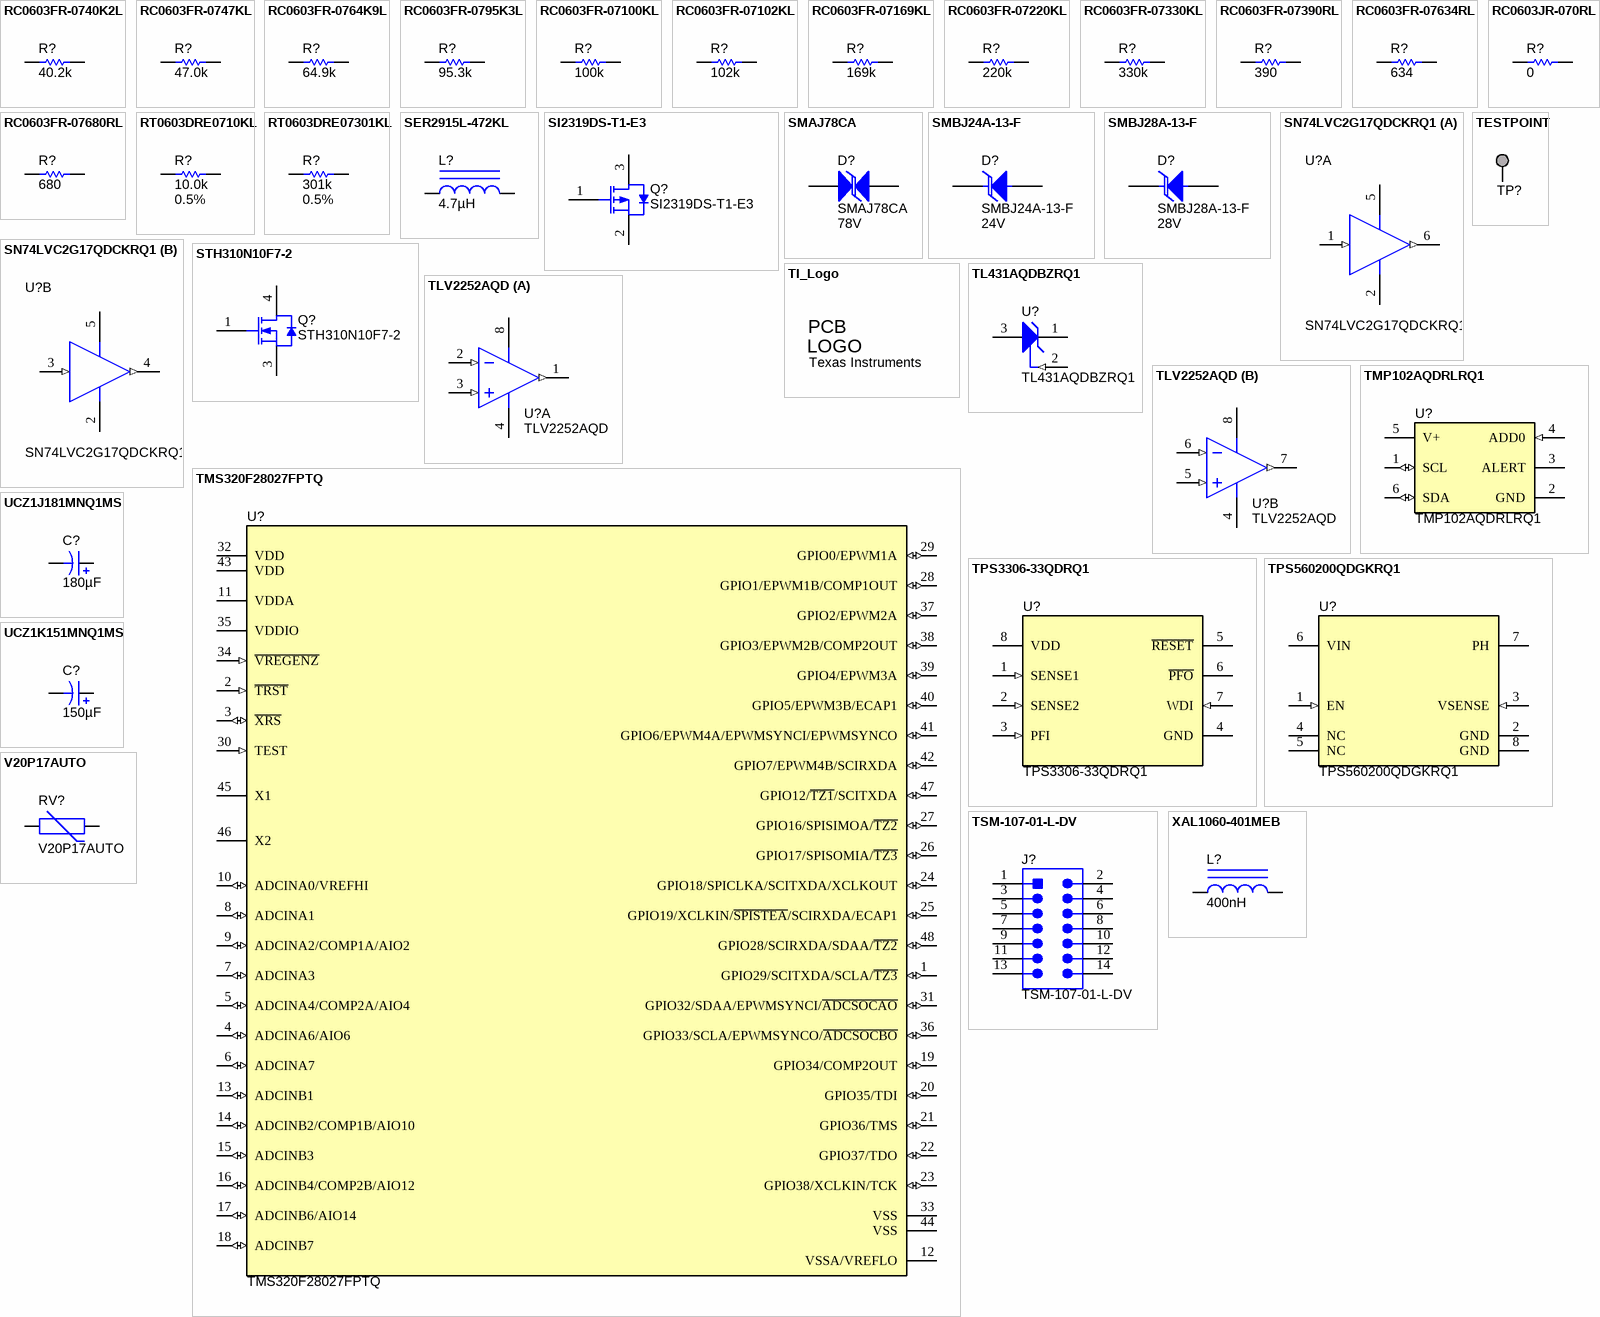
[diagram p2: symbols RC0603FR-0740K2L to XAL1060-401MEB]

## RC0603FR-0740K2L
designator R?  ValueDisplayed: 40.2k  (hidden comment: RC0603FR-0740K2L)
RES, 40.2 k, 1%, 0.1 W, 0603; Manufacturer: Yageo America; CompType: Resistor; Value: 40.2k; Res_ohm: 40200; Value_Code: 40k2; Tolerance_%: 1; Power_W: 0.1; Value2: 0.1W; VDC_V: 150; TempCo: 200 ppm/C; EIA_Code: E96; U/M: EA; AEC Category: Q200; SizeArea_mm2: 1.28; SizeX_mm: 1.6; SizeY_mm: 0.8
signal-integrity model Resistor
simulation model Resistor
footprint 0603
footprint 0603M
footprint 0603L
footprint 0603_HV
footprint 0603S
pins: 1, 2

## RC0603FR-0747KL
designator R?  ValueDisplayed: 47.0k  (hidden comment: RC0603FR-0747KL)
RES, 47.0 k, 1%, 0.1 W, 0603; Manufacturer: Yageo America; CompType: Resistor; Value: 47.0k; Res_ohm: 47000; Value_Code: 47k0; Tolerance_%: 1; Power_W: 0.1; Value2: 0.1W; VDC_V: 150; TempCo: 200 ppm/C; U/M: EA; AEC Category: Q200; SizeArea_mm2: 1.28; SizeX_mm: 1.6; SizeY_mm: 0.8
signal-integrity model Resistor
simulation model Resistor
footprint 0603
footprint 0603M
footprint 0603L
footprint 0603_HV
footprint 0603S
pins: 1, 2

## RC0603FR-0764K9L
designator R?  ValueDisplayed: 64.9k  (hidden comment: RC0603FR-0764K9L)
RES, 64.9 k, 1%, 0.1 W, 0603; Manufacturer: Yageo America; CompType: Resistor; Value: 64.9k; Res_ohm: 64900; Value_Code: 64k9; Tolerance_%: 1; Power_W: 0.1; Value2: 0.1W; VDC_V: 150; TempCo: 200 ppm/C; EIA_Code: E96; U/M: EA; AEC Category: Q200; SizeArea_mm2: 1.28; SizeX_mm: 1.6; SizeY_mm: 0.8
signal-integrity model Resistor
simulation model Resistor
footprint 0603
footprint 0603M
footprint 0603L
footprint 0603_HV
footprint 0603S
pins: 1, 2

## RC0603FR-0795K3L
designator R?  ValueDisplayed: 95.3k  (hidden comment: RC0603FR-0795K3L)
RES, 95.3 k, 1%, 0.1 W, 0603; Manufacturer: Yageo America; CompType: Resistor; Value: 95.3k; Res_ohm: 95300; Value_Code: 95k3; Tolerance_%: 1; Power_W: 0.1; Value2: 0.1W; VDC_V: 150; TempCo: 200 ppm/C; EIA_Code: E96; U/M: EA; AEC Category: Q200; SizeArea_mm2: 1.28; SizeX_mm: 1.6; SizeY_mm: 0.8
signal-integrity model Resistor
simulation model Resistor
footprint 0603
footprint 0603M
footprint 0603L
footprint 0603_HV
footprint 0603S
pins: 1, 2

## RC0603FR-07100KL
designator R?  ValueDisplayed: 100k  (hidden comment: RC0603FR-07100KL)
RES, 100 k, 1%, 0.1 W, 0603; Manufacturer: Yageo America; CompType: Resistor; Value: 100k; Res_ohm: 100000; Tolerance_%: 1; Power_W: 0.1; Value2: 0.1W; VDC_V: 150; TempCo: 200 ppm/C; SizeArea_mm2: 1.28; SizeX_mm: 1.6; SizeY_mm: 0.8; EIA_Code: E96; U/M: EA; AEC Category: Q200
signal-integrity model Resistor
simulation model Resistor
footprint 0603
footprint 0603M
footprint 0603L
footprint 0603_HV
footprint 0603S
pins: 1, 2

## RC0603FR-07102KL
designator R?  ValueDisplayed: 102k  (hidden comment: RC0603FR-07102KL)
RES, 102 k, 1%, 0.1 W, 0603; Manufacturer: Yageo America; CompType: Resistor; Value: 102k; Res_ohm: 102000; Tolerance_%: 1; Power_W: 0.1; Value2: 0.1W; VDC_V: 150; TempCo: 200 ppm/C; EIA_Code: E96; U/M: EA; AEC Category: Q200; SizeArea_mm2: 1.28; SizeX_mm: 1.6; SizeY_mm: 0.8
signal-integrity model Resistor
simulation model Resistor
footprint 0603
footprint 0603M
footprint 0603L
footprint 0603_HV
footprint 0603S
pins: 1, 2

## RC0603FR-07169KL
designator R?  ValueDisplayed: 169k  (hidden comment: RC0603FR-07169KL)
RES, 169 k, 1%, 0.1 W, 0603; Manufacturer: Yageo America; CompType: Resistor; Value: 169k; Res_ohm: 169000; Tolerance_%: 1; Power_W: 0.1; Value2: 0.1W; VDC_V: 150; TempCo: 200 ppm/C; EIA_Code: E96; U/M: EA; AEC Category: Q200; SizeArea_mm2: 1.28; SizeX_mm: 1.6; SizeY_mm: 0.8
signal-integrity model Resistor
simulation model Resistor
footprint 0603
footprint 0603M
footprint 0603L
footprint 0603_HV
footprint 0603S
pins: 1, 2

## RC0603FR-07220KL
designator R?  ValueDisplayed: 220k  (hidden comment: RC0603FR-07220KL)
RES, 220 k, 1%, 0.1 W, 0603; Manufacturer: Yageo America; CompType: Resistor; Value: 220k; Res_ohm: 220000; Tolerance_%: 1; Power_W: 0.1; Value2: 0.1W; VDC_V: 150; TempCo: 200 ppm/C; SizeArea_mm2: 1.28; SizeX_mm: 1.6; SizeY_mm: 0.8; U/M: EA; AEC Category: Q200
signal-integrity model Resistor
simulation model Resistor
footprint 0603
footprint 0603M
footprint 0603L
footprint 0603_HV
footprint 0603S
pins: 1, 2

## RC0603FR-07330KL
designator R?  ValueDisplayed: 330k  (hidden comment: RC0603FR-07330KL)
RES, 330 k, 1%, 0.1 W, 0603; Manufacturer: Yageo America; CompType: Resistor; Value: 330k; Res_ohm: 330000; Tolerance_%: 1; Power_W: 0.1; Value2: 0.1W; VDC_V: 150; TempCo: 200 ppm/C; U/M: EA; AEC Category: Q200; SizeArea_mm2: 1.28; SizeX_mm: 1.6; SizeY_mm: 0.8
signal-integrity model Resistor
simulation model Resistor
footprint 0603
footprint 0603M
footprint 0603L
footprint 0603_HV
footprint 0603S
pins: 1, 2

## RC0603FR-07390RL
designator R?  ValueDisplayed: 390  (hidden comment: RC0603FR-07390RL)
RES, 390, 1%, 0.1 W, 0603; Manufacturer: Yageo America; CompType: Resistor; Value: 390; Value_Code: 390R; Tolerance_%: 1; Power_W: 0.1; Value2: 0.1W; VDC_V: 150; TempCo: 200 ppm/C; U/M: EA; AEC Category: Q200; SizeArea_mm2: 1.28; SizeX_mm: 1.6; SizeY_mm: 0.8
signal-integrity model Resistor
simulation model Resistor
footprint 0603
footprint 0603M
footprint 0603L
footprint 0603_HV
footprint 0603S
pins: 1, 2

## RC0603FR-07634RL
designator R?  ValueDisplayed: 634  (hidden comment: RC0603FR-07634RL)
RES, 634, 1%, 0.1 W, 0603; Manufacturer: Yageo America; CompType: Resistor; Value: 634; Value_Code: 634R; Tolerance_%: 1; Power_W: 0.1; Value2: 0.1W; VDC_V: 150; TempCo: 200 ppm/C; EIA_Code: E96; U/M: EA; AEC Category: Q200; SizeArea_mm2: 1.28; SizeX_mm: 1.6; SizeY_mm: 0.8
signal-integrity model Resistor
simulation model Resistor
footprint 0603
footprint 0603M
footprint 0603L
footprint 0603_HV
footprint 0603S
pins: 1, 2

## RC0603FR-07680RL
designator R?  ValueDisplayed: 680  (hidden comment: RC0603FR-07680RL)
RES, 680, 1%, 0.1 W, 0603; Manufacturer: Yageo America; CompType: Resistor; Value: 680; Value_Code: 680R; Tolerance_%: 1; Power_W: 0.1; Value2: 0.1W; VDC_V: 150; TempCo: 200 ppm/C; U/M: EA; AEC Category: Q200; SizeArea_mm2: 1.28; SizeX_mm: 1.6; SizeY_mm: 0.8
signal-integrity model Resistor
simulation model Resistor
footprint 0603
footprint 0603M
footprint 0603L
footprint 0603_HV
footprint 0603S
pins: 1, 2

## RC0603JR-070RL
designator R?  ValueDisplayed: 0  (hidden comment: RC0603JR-070RL)
RES, 0, 5%, 0.1 W, 0603; Manufacturer: Yageo America; CompType: Resistor; Value: 0; Value_Code: 0000; Tolerance_%: 5; Power_W: 0.1; Value2: 0.1W; VDC_V: 50; TempCo: 200 ppm/C; EIA_Code: E24; U/M: EA; AEC Category: Q200; SizeArea_mm2: 1.28; SizeX_mm: 1.6; SizeY_mm: 0.8; SizeZ_mm: 1
signal-integrity model Resistor
simulation model Resistor
footprint 0603
footprint 0603M
footprint 0603L
footprint 0603_HV
footprint 0603S
pins: 1, 2

## RT0603DRE0710KL
designator R?  ValueDisplayed: 10.0k  Value1: 0.5%  (hidden comment: RT0603DRE0710KL)
RES, 10.0 k, 0.5%, 0.1 W, 0603; Manufacturer: Yageo America; CompType: Resistor; Value: 10.0k; Res_ohm: 10000; Value_Code: 10k0; Tolerance_%: 0.5; Power_W: 0.1; Value2: 0.1W; VDC_V: 75; TempCo: 50 ppm/C; EIA_Code: E192; U/M: EA; AEC Category: Q200; SizeArea_mm2: 1.28; SizeX_mm: 1.6; SizeY_mm: 0.8; SizeZ_mm: 1
signal-integrity model Resistor
simulation model Resistor
footprint 0603
footprint 0603M
footprint 0603L
footprint 0603_HV
footprint 0603S
pins: 1, 2

## RT0603DRE07301KL
designator R?  ValueDisplayed: 301k  Value1: 0.5%  (hidden comment: RT0603DRE07301KL)
RES, 301 k, 0.5%, 0.1 W, 0603; Manufacturer: Yageo America; CompType: Resistor; Value: 301k; Res_ohm: 301000; Tolerance_%: 0.5; Power_W: 0.1; Value2: 0.1W; VDC_V: 75; TempCo: 50 ppm/C; EIA_Code: E192; U/M: EA; AEC Category: Q200; SizeArea_mm2: 1.28; SizeX_mm: 1.6; SizeY_mm: 0.8; SizeZ_mm: 1
signal-integrity model Resistor
simulation model Resistor
footprint 0603
footprint 0603M
footprint 0603L
footprint 0603_HV
footprint 0603S
pins: 1, 2

## SER2915L-472KL
designator L?  ValueDisplayed: 4.7µH  (hidden comment: SER2915L-472KL)
Inductor, Shielded E Core, Ferrite, 4.7 µH, 30 A, 0.0015 ohm, SMD; Manufacturer: Coilcraft; Value: 4.7uH; Ind_H: 4.7E-6; Imax_A: 30; Irms: 30A @ 40C rise; Isat: 39A @ 30% inductance drop; DCR_ohm: 0.0015; Value2: 30A; AEC Category: Q200
signal-integrity model Inductor
simulation model Inductor
footprint SER2915L
pins: 1, 2

## SI2319DS-T1-E3
designator Q?
MOSFET, P-CH, -40 V, -2.3 A, SOT-23; Manufacturer: Vishay-Siliconix; Alternate Manufacturer: None; U/M: EA; ChType: P; Value: -40V; Value1: 0.13 ohm; Rdson45_ohm: 0.13; Value2: 11.3 nC; QgTyp_nC: 11.3; Vgs_V: -20; SizeAreaWB_mm2: 14; SizeArea_mm2: 7.5; SizeX_mm: 2.5; SizeY_mm: 3; SizeZ_mm: 1.1; AEC Category: Q101
footprint SOT-23
footprint SOT-23M
footprint SOT-23L
simulation model Si2319DS
pins: 1 G, 2 S, 3 D

## SMAJ78CA
designator D?  value 78V
Diode, TVS, Bi, 78 V, SMA; Manufacturer: Littelfuse; U/M: EA; Power_W: 3.3; Vr_V: 78; Value1: 3.3W; RJA_CperW: 120; SizeAreaWB_mm2: 37.3428; SizeArea_mm2: 16.3228; SizeX_mm: 5.59; SizeY_mm: 2.92; SizeZ_mm: 2.87; AEC Category: Q101
footprint SMA
pins: 1, 2

## SMBJ24A-13-F
designator D?  value 24V
Diode, TVS, Uni, 24 V, 600 W, SMB; Manufacturer: Diodes Inc.; U/M: EA; Power_W: 5; Vr_V: 24; Value1: 5W; SizeAreaWB_mm2: 44.156; SizeArea_mm2: 21.336; SizeX_mm: 5.6; SizeY_mm: 3.81; SizeZ_mm: 2.6; AEC Category: Q101
footprint SMB
pins: 1 K, 2 A

## SMBJ28A-13-F
designator D?  value 28V
Diode, TVS, Uni, 28 V, 600 W, SMB; Manufacturer: Diodes Inc.; U/M: EA; Power_W: 5; Vr_V: 28; Value1: 5W; SizeAreaWB_mm2: 44.156; SizeArea_mm2: 21.336; SizeX_mm: 5.6; SizeY_mm: 3.81; SizeZ_mm: 2.6; AEC Category: Q101
footprint SMB
pins: 1 K, 2 A

## SN74LVC2G17QDCKRQ1
designator U?
Dual Schmitt Trigger Buffer, DCK0006A; Manufacturer: Texas Instruments; SymbolCreator: Altium; SizeArea_mm2: 4.2; SizeAreaWB_mm2: 9.3; SizeX_mm: 2.1; SizeY_mm: 2; SizeZ_mm: 1.1; CompType: IC; U/M: EA
footprint DCK0006A_N
footprint DCK0006A_M
footprint DCK0006A_L
pins on every part: 2 GND (power), 5 VCC (power)
part A pins: 1 1A (in), 6 1Y (out)
part B pins: 3 2A (in), 4 2Y (out)
1 alternate drawing of the same symbol

## STH310N10F7-2
designator Q?
MOSFET, N-CH, 100 V, 180 A, DDPAK; Manufacturer: STMicroelectronics; Alternate Manufacturer: None; U/M: EA; ChType: N; Value: 100V; VdsMax_V: 100; Value1: ? ohm; Value2: 180 nC; QgTyp_nC: 180; Vgs_V: 20; SizeAreaWB_mm2: 209.6992; SizeArea_mm2: 154.8892; SizeX_mm: 15.245; SizeY_mm: 10.16; SizeZ_mm: 4.445; AEC Category: Q101
footprint DDPAK
pins: 1 G, 3 S, 4 D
